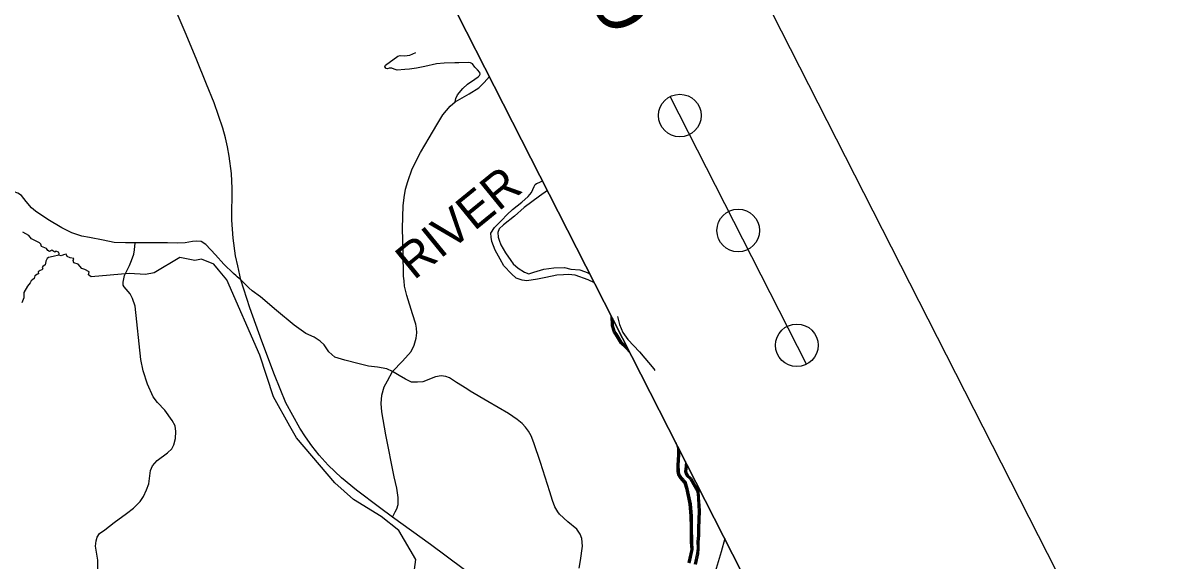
# Model space of a CAD drawing. Extents: x 558484 to 564063, y 513718 to 518374.
# Drawn here: x 559464.9 to 559681.5, y 515001 to 515102.2 of the extents above; entities that cross this region are included whole.
import ezdxf

# ---------------------------------------------------------------- set-up
doc = ezdxf.new("R2010")
doc.units = 0
doc.layers.add('Default', color=7, linetype='Continuous')
doc.layers.add('Prop Shade Heavy', color=7, linetype='Continuous')

msp = doc.modelspace()

# ---------------------------------------------------------------- linework, layer by layer
at = {"layer": 'Default'}
for points in [[(559691.68, 514819.14), (559493.11, 515209.15), (559540.17, 515233.11), (559738.74, 514843.1)], [(559363.74, 514652.18), (559165.18, 515042.19), (559493.11, 515209.15), (559691.68, 514819.14)], [(559363.74, 514652.18), (559165.18, 515042.19), (559493.11, 515209.15), (559691.68, 514819.14)]]:
    msp.add_lwpolyline(points, close=True, dxfattribs=at)
for points in [[(559505.86, 515053.88), (559505.3, 515056.52), (559504.87, 515058.41), (559504.42, 515061.77), (559504.21, 515065.15), (559504.22, 515067.34), (559504.24, 515069.08), (559504.23, 515071.07), (559504.11, 515073.92), (559503.7, 515077.15), (559503.39, 515078.93), (559503, 515080.65), (559502.52, 515082.47), (559500.89, 515087.19), (559499.42, 515090.74), (559497.49, 515095.52), (559495.39, 515100.53), (559493.15, 515105.76), (559491.27, 515109.99), (559488.76, 515115.97), (559485.92, 515123.14), (559482.67, 515130.71)], [(559546.22, 515087.42), (559546.33, 515088.03), (559546.67, 515088.7), (559547.63, 515089.9), (559548.51, 515090.74), (559549.91, 515091.66), (559550.55, 515092.09), (559550.78, 515092.36), (559550.9, 515092.62), (559550.83, 515092.94), (559550.41, 515093.39), (559549.94, 515093.92), (559549.48, 515094.53), (559549.09, 515094.74), (559548.65, 515094.79), (559546.87, 515094.72), (559546.12, 515094.75), (559544.12, 515094.7), (559542.72, 515094.53), (559540.53, 515094.06), (559538.94, 515093.74), (559537.63, 515093.52), (559536.71, 515093.5), (559535.31, 515093.38), (559534.75, 515093.57), (559534.29, 515093.74), (559533.8, 515093.75), (559533.48, 515093.6), (559533.25, 515093.66), (559532.98, 515094), (559533.12, 515094.27), (559535.45, 515095.96), (559535.86, 515096.09), (559536.69, 515096.03), (559537.66, 515096.17), (559538.83, 515096.7)], [(559546.22, 515087.42), (559548.83, 515088.9), (559550.64, 515090.04), (559551.67, 515091.05), (559552.68, 515092.15)], [(559534.39, 515036.68), (559536.3, 515038.59), (559537.96, 515040.41), (559538.51, 515041.61), (559538.86, 515042.9), (559538.97, 515043.9), (559538.96, 515044.78), (559538.78, 515045.58), (559538.17, 515047.53), (559537.14, 515050.97), (559536.7, 515052.7), (559536.6, 515053.7), (559536.5, 515054.57), (559536.4, 515059.07), (559536.29, 515063.61), (559536.41, 515067.83), (559536.59, 515069.42), (559536.86, 515070.93), (559537.29, 515072.38), (559538.1, 515074.81), (559539.7, 515077.83), (559541.33, 515080.63), (559542.74, 515083.05), (559543.9, 515084.96), (559545.28, 515086.55), (559546.22, 515087.42)], [(559565.32, 515054.75), (559563.24, 515054.34), (559561.7, 515054.04), (559559.72, 515053.71), (559558.8, 515053.83), (559557.69, 515054.24), (559556.8, 515055.05), (559555.35, 515056.54), (559554.65, 515057.78), (559553.73, 515059.5), (559553.08, 515061.13), (559552.96, 515061.95), (559552.94, 515062.68), (559553.63, 515063.75), (559554.92, 515065.09), (559556.02, 515066.21), (559556.97, 515067.11), (559558.77, 515068.52), (559559.93, 515069.61), (559560.6, 515070.34), (559561.07, 515071.45), (559561.26, 515071.81), (559561.51, 515072.04), (559562.01, 515072.19), (559562.66, 515072.55)], [(559486.02, 515060.86), (559484.17, 515060.85), (559482.08, 515060.94), (559479.98, 515061.39), (559477.41, 515061.86), (559475.98, 515062.13), (559474.09, 515062.76), (559472.18, 515063.7), (559469.59, 515065.27), (559467.24, 515066.8), (559466.47, 515067.45), (559465.47, 515068.64), (559465.08, 515069.23), (559464.6, 515069.76), (559463.92, 515070.2), (559463.26, 515070.45)], [(559562.09, 515069.65), (559559.21, 515067.52), (559557.39, 515065.87), (559555.32, 515064.26), (559554.47, 515063.48), (559554.23, 515062.8), (559554.28, 515061.94), (559554.46, 515061.38), (559554.8, 515060.5), (559555.69, 515058.98), (559556.69, 515057.53), (559557.14, 515056.93), (559558.08, 515056.07), (559559.23, 515055.34), (559560.04, 515055.02), (559560.99, 515055.32), (559562.88, 515055.89), (559564.77, 515056.13), (559566.76, 515056.23), (559568, 515055.93), (559569.66, 515055.76), (559571.26, 515055.19), (559571.56, 515055.06)], [(559563.58, 515070.73), (559562.09, 515069.65)], [(559501.66, 515055.8), (559500.8, 515056.83), (559498.51, 515057.8), (559497.23, 515057.51), (559494.39, 515058.09), (559489.57, 515055.21), (559487.95, 515054.91), (559484.9, 515055.11), (559477.7, 515054.44), (559477.19, 515054.82), (559477.34, 515055.43), (559476.55, 515055.85), (559475.99, 515056.06), (559475.26, 515056.84), (559474.47, 515057.1), (559474.34, 515057.51), (559474.46, 515057.93), (559473.77, 515058.06), (559473.18, 515058.29), (559473.04, 515058.73), (559472.49, 515058.58), (559472.09, 515058.39), (559471.66, 515058.55), (559471.69, 515058.83), (559471.6, 515059.11), (559471.1, 515059.29), (559470.88, 515059.09), (559470.33, 515059.51), (559470.11, 515059.36), (559469.87, 515059.26), (559469.58, 515059.41), (559469.29, 515059.8), (559468.37, 515060.18), (559468.27, 515060.61), (559468.02, 515060.84), (559466.51, 515061.6), (559466, 515062.24), (559464.86, 515062.89)], [(559478.96, 514999.55), (559478.97, 515001.16), (559478.53, 515003.78), (559478.65, 515004.8), (559478.88, 515005.5), (559479.27, 515006.16), (559480.32, 515006.88), (559482.02, 515008.21), (559484.39, 515009.95), (559485.68, 515010.94), (559486.96, 515012.21), (559487.59, 515013.15), (559488.16, 515014.36), (559488.59, 515015.54), (559488.88, 515018.01), (559489.26, 515018.93), (559490.12, 515019.89), (559492.07, 515021.35), (559492.88, 515022.08), (559493.25, 515022.88), (559493.59, 515024.07), (559493.66, 515025.36), (559493.52, 515026.41), (559492.99, 515027.46), (559491.57, 515029.37), (559490.22, 515030.85), (559489.41, 515031.88), (559488.31, 515034.3), (559487.51, 515036.78), (559487.08, 515038.93), (559486.01, 515048.92), (559485.49, 515050.42), (559485.04, 515051.24), (559483.92, 515052.56), (559483.77, 515052.88), (559483.72, 515053.44), (559483.99, 515054.74), (559484.92, 515056.57), (559485.34, 515057.51), (559485.72, 515058.74), (559485.89, 515059.53), (559486.02, 515060.86)], [(559505.86, 515053.88), (559505.18, 515054.45), (559504.98, 515054.64), (559504.51, 515055.12), (559502.71, 515056.85), (559501.13, 515058.58), (559499.3, 515060.54), (559498.41, 515061.13), (559497.58, 515061.2), (559496.77, 515061.1), (559495.4, 515060.89), (559494.01, 515060.79), (559492.08, 515060.85), (559486.02, 515060.86)], [(559471.66, 515058.55), (559470.55, 515058.28), (559469.72, 515058.08), (559469.44, 515057.93), (559469.18, 515057.41), (559469.11, 515056.98), (559469.04, 515056.7), (559468.64, 515056.43), (559468.5, 515056.21), (559468.61, 515055.94), (559468.45, 515055.76), (559468.11, 515055.66), (559467.77, 515055.41), (559467.82, 515055.04), (559467.65, 515054.96), (559467.15, 515054.67), (559467.02, 515054.17), (559466.72, 515053.99), (559466.44, 515053.7), (559466.27, 515053.33), (559465.75, 515052.68), (559465.05, 515051.54), (559465.03, 515050.53), (559464.67, 515049.56)], [(559515.1, 515026.36), (559512.01, 515031.91), (559509.46, 515039.75), (559503.23, 515053.93), (559501.66, 515055.8)], [(559572.45, 515053.32), (559571.23, 515053.93), (559568.8, 515054.81), (559567.55, 515054.89), (559566.6, 515054.87), (559565.32, 515054.75)], [(559534.39, 515036.68), (559533.36, 515037.14), (559531.62, 515037.44), (559529.89, 515037.64), (559528.17, 515038.07), (559525.48, 515038.79), (559523.54, 515039.37), (559522.41, 515040.37), (559521.57, 515041.64), (559520.81, 515042.38), (559519.68, 515043.11), (559518.09, 515043.79), (559515.9, 515045.34), (559512.58, 515048.15), (559509.61, 515050.68), (559508.02, 515051.86), (559507.36, 515052.37), (559505.86, 515053.88)], [(559534.42, 515009.27), (559532, 515011.07), (559527.62, 515014.32), (559524.85, 515016.64), (559522.34, 515019.02), (559520.62, 515020.93), (559519.22, 515022.66), (559518.04, 515024.34), (559516.99, 515025.96), (559514.34, 515030.74), (559512.22, 515036.02), (559509.84, 515042.39), (559507.58, 515048.63), (559505.86, 515053.88)], [(559579.28, 515039.91), (559579.11, 515040.09), (559578.26, 515041.04), (559577.32, 515041.95), (559576.36, 515043.51), (559575.99, 515044.08), (559575.6, 515045.22), (559575.55, 515047.22)], [(559578.97, 515040.51), (559578.39, 515041.17), (559577.46, 515042.06), (559576.51, 515043.6), (559576.15, 515044.16), (559575.78, 515045.25), (559575.75, 515046.56)], [(559578.59, 515041.25), (559578.54, 515041.31), (559577.62, 515042.19), (559576.69, 515043.72), (559576.34, 515044.25), (559575.99, 515045.29), (559575.96, 515046.63)], [(559576.73, 515047.02), (559577.15, 515045.52), (559577.73, 515043.98), (559578.67, 515042.67), (559580.9, 515040.34), (559583.56, 515037.14), (559583.79, 515036.81)], [(559534.42, 515009.27), (559534.93, 515010.23), (559535.24, 515010.82), (559535.46, 515011.63), (559535.46, 515012.92), (559535.21, 515014.69), (559534.74, 515016.81), (559533.15, 515024.73), (559532.41, 515029.08), (559532.29, 515030.62), (559532.41, 515032.2), (559532.87, 515033.77), (559533.46, 515034.92), (559534.39, 515036.68)], [(559569.57, 514999.62), (559569.77, 515001.12), (559570.14, 515003.76), (559570.02, 515005.24), (559569.71, 515006.07), (559569.11, 515006.96), (559567.43, 515008.34), (559565.83, 515009.78), (559565.53, 515010.22), (559564.99, 515011.17), (559564.54, 515012.39), (559564.02, 515014), (559562.25, 515019.5), (559560.99, 515023.21), (559560.5, 515024.57), (559560.03, 515025.44), (559559.47, 515026.17), (559558.81, 515026.89), (559557.86, 515027.64), (559556.22, 515028.77), (559552.34, 515031.02), (559549.02, 515032.98), (559548.42, 515033.39), (559546.46, 515034.61), (559545.13, 515035.49), (559544.44, 515035.74), (559543.6, 515035.82), (559542.48, 515035.62), (559540.11, 515034.73), (559539.14, 515034.62), (559537.97, 515034.66), (559536.84, 515035.18), (559535.68, 515035.92), (559534.39, 515036.68)], [(559532.29, 514987.11), (559535.95, 514989.73), (559538.63, 514994.65), (559538.33, 514997.51), (559538.78, 515001.28), (559535.64, 515006.71), (559532.31, 515009.36), (559527.11, 515012.58), (559523.6, 515015.71), (559516.33, 515024.15), (559515.1, 515026.36)], [(559590.06, 515000.69), (559590.61, 515003.18), (559590.51, 515004.53), (559590.47, 515007.34), (559590.45, 515009.41), (559590.26, 515011.72), (559589.7, 515014.48), (559589.31, 515015.67), (559588.55, 515016.53), (559588.12, 515017.22), (559588, 515017.84), (559587.99, 515019.05), (559588.08, 515020.97), (559588.1, 515022.22), (559587.76, 515023.24), (559587.75, 515023.26)], [(559590.24, 515000.65), (559590.79, 515003.17), (559590.69, 515004.54), (559590.65, 515007.34), (559590.63, 515009.42), (559590.44, 515011.74), (559589.87, 515014.53), (559589.46, 515015.76), (559588.69, 515016.63), (559588.29, 515017.28), (559588.18, 515017.86), (559588.17, 515019.04), (559588.26, 515020.97), (559588.27, 515022.24)], [(559590.44, 515000.59), (559591.01, 515003.15), (559590.9, 515004.55), (559590.86, 515007.34), (559590.84, 515009.42), (559590.65, 515011.77), (559590.08, 515014.58), (559589.65, 515015.87), (559588.86, 515016.76), (559588.49, 515017.36), (559588.39, 515017.88), (559588.38, 515019.04), (559588.47, 515020.96), (559588.48, 515021.83)], [(559589.56, 515019.71), (559589.5, 515018.8)], [(559589.5, 515018.8), (559589.33, 515017.85), (559589.53, 515017.28), (559589.76, 515016.93), (559590.37, 515016.37), (559591.19, 515014.94), (559591.69, 515014.09), (559591.78, 515012.94), (559591.89, 515011.4), (559591.92, 515010.42), (559591.86, 515008.76), (559591.83, 515007.18), (559591.81, 515005.82), (559591.67, 515004.64), (559591.72, 515003.41), (559591.61, 515002.4), (559591.2, 515000.43)], [(559589.73, 515018.76), (559589.57, 515017.87), (559589.74, 515017.38), (559589.94, 515017.07), (559590.55, 515016.51), (559591.39, 515015.05), (559591.91, 515014.16), (559592, 515012.96), (559592.12, 515011.41), (559592.15, 515010.41), (559592.09, 515008.76), (559592.05, 515007.18), (559592.03, 515005.81), (559591.9, 515004.63), (559591.94, 515003.4), (559591.84, 515002.37), (559591.42, 515000.38)], [(559589.86, 515018.74), (559589.71, 515017.88), (559589.86, 515017.44), (559590.04, 515017.16), (559590.66, 515016.6), (559591.51, 515015.12), (559592.04, 515014.2), (559592.14, 515012.97), (559592.25, 515011.42), (559592.28, 515010.41), (559592.22, 515008.75), (559592.19, 515007.18), (559592.17, 515005.8), (559592.03, 515004.62), (559592.08, 515003.4), (559591.97, 515002.35), (559591.55, 515000.35)], [(559589.76, 515019.31), (559589.73, 515018.76)], [(559589.88, 515019.08), (559589.86, 515018.74)], [(559590.01, 515018.82), (559589.86, 515018.74)], [(559570.71, 514982.21), (559570, 514982.82), (559567.87, 514984.55), (559564.86, 514986.8), (559561.93, 514989), (559552.97, 514995.65), (559547.73, 514999.51), (559541.55, 515004.12), (559534.42, 515009.27)], [(559596.94, 515005.22), (559596.24, 515002.74), (559593.62, 514993.94), (559591.67, 514987.73), (559591.33, 514986.8)]]:
    msp.add_lwpolyline(points, dxfattribs=at)
at = {"layer": 'Prop Shade Heavy'}
msp.add_line((559612.32, 515038.01), (559586.67, 515088.4), dxfattribs=at)
for centre in [(559588.48, 515084.81), (559599.47, 515063.19), (559610.49, 515041.58)]:
    msp.add_circle(centre, 4.01, dxfattribs=at)

# ---------------------------------------------------------------- texts
at = {"layer": 'Default'}
msp.add_text('RIVER', height=6.562, rotation=39.1736, dxfattribs=at).set_placement((559538.46, 515053.73))
at = {"layer": 'Prop Shade Heavy'}
msp.add_text('OFFSITE DETOUR', height=10, rotation=116.9819, dxfattribs=at).set_placement((559584.17, 515103.73))

doc.saveas('drawing.dxf')
